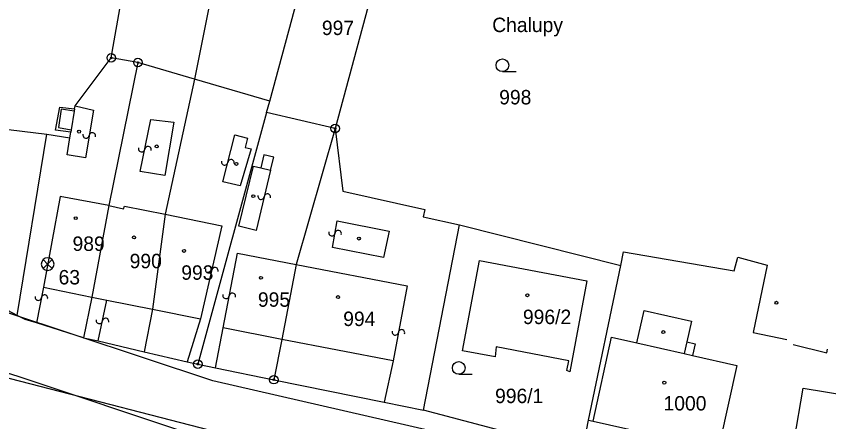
# Model space of a CAD drawing. Extents: x -469926 to -462499, y -1098642 to -1092733.
# Drawn here: x -465801.9 to -465706.1, y -1094414.1 to -1094366.3 of the extents above; entities that cross this region are included whole.
import ezdxf

# ---------------------------------------------------------------- set-up
doc = ezdxf.new("R2010")
doc.units = 0
for name, color, linetype in [('Vrstva 1', 7, 'Continuous'), ('Vrstva 14', 7, 'Continuous'), ('Vrstva 24', 7, 'Continuous'), ('Vrstva 25', 7, 'Continuous'), ('Vrstva 4', 7, 'Continuous'), ('Vrstva 50', 7, 'Continuous'), ('Vrstva 51', 7, 'Continuous'), ('Vrstva 8', 7, 'Continuous')]:
    doc.layers.add(name, color=color, linetype=linetype)

msp = doc.modelspace()

# ---------------------------------------------------------------- linework, layer by layer
at = {"layer": 'Vrstva 1'}
for p, q in [((-465790.66, -1094371.21), (-465786.86, -1094349.53)), ((-465776.39, -1094351.58), (-465780.87, -1094373.7)), ((-465771.99, -1094376.29), (-465765.81, -1094353.65)), ((-465757.73, -1094355.32), (-465764.28, -1094379.53)), ((-465794.93, -1094376.84), (-465790.66, -1094371.21)), ((-465794.93, -1094376.84), (-465790.66, -1094371.21)), ((-465787.52, -1094371.76), (-465790.94, -1094388.6)), ((-465787.52, -1094371.76), (-465790.94, -1094388.6)), ((-465787.52, -1094371.76), (-465790.66, -1094371.21)), ((-465787.52, -1094371.76), (-465790.66, -1094371.21)), ((-465780.87, -1094373.7), (-465787.52, -1094371.76)), ((-465780.87, -1094373.7), (-465787.52, -1094371.76)), ((-465780.87, -1094373.7), (-465784.33, -1094389.64)), ((-465780.87, -1094373.7), (-465784.33, -1094389.64)), ((-465771.99, -1094376.29), (-465780.87, -1094373.7)), ((-465771.99, -1094376.29), (-465780.87, -1094373.7)), ((-465794.98, -1094377.2), (-465794.93, -1094376.84)), ((-465794.98, -1094377.2), (-465794.93, -1094376.84)), ((-465772.36, -1094377.64), (-465771.99, -1094376.29)), ((-465772.36, -1094377.64), (-465771.99, -1094376.29)), ((-465797.22, -1094379.71), (-465796.74, -1094377.02)), ((-465797.22, -1094379.71), (-465796.74, -1094377.02)), ((-465796.74, -1094377.02), (-465794.98, -1094377.2)), ((-465796.74, -1094377.02), (-465794.98, -1094377.2)), ((-465772.36, -1094377.64), (-465780.46, -1094407.29)), ((-465772.36, -1094377.64), (-465780.46, -1094407.29)), ((-465764.28, -1094379.53), (-465772.36, -1094377.64)), ((-465764.28, -1094379.53), (-465772.36, -1094377.64)), ((-465812.27, -1094378.47), (-465798.24, -1094380.2)), ((-465812.27, -1094378.47), (-465798.24, -1094380.2)), ((-465795.43, -1094379.97), (-465797.22, -1094379.71)), ((-465795.43, -1094379.97), (-465797.22, -1094379.71)), ((-465764.28, -1094379.53), (-465768.87, -1094395.55)), ((-465764.28, -1094379.53), (-465768.87, -1094395.55)), ((-465764.28, -1094379.53), (-465763.36, -1094386.92)), ((-465764.28, -1094379.53), (-465763.36, -1094386.92)), ((-465801.74, -1094401.55), (-465798.24, -1094380.2)), ((-465801.74, -1094401.55), (-465798.24, -1094380.2)), ((-465798.24, -1094380.2), (-465795.54, -1094380.64)), ((-465798.24, -1094380.2), (-465795.54, -1094380.64)), ((-465795.54, -1094380.64), (-465795.43, -1094379.97)), ((-465795.54, -1094380.64), (-465795.43, -1094379.97)), ((-465763.36, -1094386.92), (-465753.69, -1094389.08)), ((-465763.36, -1094386.92), (-465753.69, -1094389.08)), ((-465790.94, -1094388.6), (-465792.95, -1094399.39)), ((-465790.94, -1094388.6), (-465792.95, -1094399.39)), ((-465753.69, -1094389.08), (-465753.92, -1094389.95)), ((-465753.69, -1094389.08), (-465753.92, -1094389.95)), ((-465784.33, -1094389.64), (-465785.79, -1094400.82)), ((-465784.33, -1094389.64), (-465785.79, -1094400.82)), ((-465753.92, -1094389.95), (-465749.62, -1094390.87)), ((-465753.92, -1094389.95), (-465749.62, -1094390.87)), ((-465753.87, -1094412.7), (-465749.62, -1094390.87)), ((-465753.87, -1094412.7), (-465749.62, -1094390.87)), ((-465749.62, -1094390.87), (-465730.62, -1094395.68)), ((-465749.62, -1094390.87), (-465730.62, -1094395.68)), ((-465730.62, -1094395.68), (-465730.29, -1094394.07)), ((-465730.62, -1094395.68), (-465730.29, -1094394.07)), ((-465730.29, -1094394.07), (-465717.26, -1094396.31)), ((-465730.29, -1094394.07), (-465717.26, -1094396.31)), ((-465801.74, -1094401.55), (-465814.21, -1094395.11)), ((-465801.74, -1094401.55), (-465814.21, -1094395.11)), ((-465749.27, -1094405.72), (-465747.25, -1094395.07)), ((-465749.27, -1094405.72), (-465747.25, -1094395.07)), ((-465747.25, -1094395.07), (-465734.63, -1094397.46)), ((-465747.25, -1094395.07), (-465734.63, -1094397.46)), ((-465717.26, -1094396.31), (-465716.83, -1094394.67)), ((-465717.26, -1094396.31), (-465716.83, -1094394.67)), ((-465716.83, -1094394.67), (-465713.36, -1094395.63)), ((-465716.83, -1094394.67), (-465713.36, -1094395.63)), ((-465768.87, -1094395.55), (-465770.57, -1094404.37)), ((-465768.87, -1094395.55), (-465770.57, -1094404.37)), ((-465734.4, -1094413.89), (-465730.62, -1094395.68)), ((-465734.4, -1094413.89), (-465730.62, -1094395.68)), ((-465734.63, -1094397.46), (-465736.6, -1094408.21)), ((-465734.63, -1094397.46), (-465736.6, -1094408.21)), ((-465792.95, -1094399.39), (-465793.93, -1094404.17)), ((-465792.95, -1094399.39), (-465793.93, -1094404.17)), ((-465785.79, -1094400.82), (-465786.79, -1094405.82)), ((-465785.79, -1094400.82), (-465786.79, -1094405.82)), ((-465800.82, -1094402.02), (-465801.74, -1094401.55)), ((-465800.82, -1094402.02), (-465801.74, -1094401.55)), ((-465799.49, -1094402.43), (-465800.82, -1094402.02)), ((-465799.49, -1094402.43), (-465800.82, -1094402.02)), ((-465793.93, -1094404.17), (-465799.49, -1094402.43)), ((-465793.93, -1094404.17), (-465799.49, -1094402.43)), ((-465793.93, -1094404.17), (-465792.21, -1094404.56)), ((-465793.93, -1094404.17), (-465792.21, -1094404.56)), ((-465792.21, -1094404.56), (-465786.79, -1094405.82)), ((-465792.21, -1094404.56), (-465786.79, -1094405.82)), ((-465770.57, -1094404.37), (-465771.5, -1094409.12)), ((-465770.57, -1094404.37), (-465771.5, -1094409.12)), ((-465745.3, -1094405.26), (-465745.41, -1094406.42)), ((-465745.3, -1094405.26), (-465745.41, -1094406.42)), ((-465736.75, -1094406.88), (-465745.3, -1094405.26)), ((-465736.75, -1094406.88), (-465745.3, -1094405.26)), ((-465786.79, -1094405.82), (-465781.7, -1094407.01)), ((-465786.79, -1094405.82), (-465781.7, -1094407.01)), ((-465745.41, -1094406.42), (-465749.27, -1094405.72)), ((-465745.41, -1094406.42), (-465749.27, -1094405.72)), ((-465781.7, -1094407.01), (-465780.46, -1094407.29)), ((-465781.7, -1094407.01), (-465780.46, -1094407.29)), ((-465780.46, -1094407.29), (-465778.38, -1094407.72)), ((-465780.46, -1094407.29), (-465778.38, -1094407.72)), ((-465736.97, -1094408.04), (-465736.75, -1094406.88)), ((-465736.97, -1094408.04), (-465736.75, -1094406.88)), ((-465778.38, -1094407.72), (-465771.5, -1094409.12)), ((-465778.38, -1094407.72), (-465771.5, -1094409.12)), ((-465736.6, -1094408.21), (-465736.97, -1094408.04)), ((-465736.6, -1094408.21), (-465736.97, -1094408.04)), ((-465766.38, -1094418.33), (-465803.8, -1094408.69)), ((-465766.38, -1094418.33), (-465803.8, -1094408.69)), ((-465771.5, -1094409.12), (-465758.48, -1094411.77)), ((-465771.5, -1094409.12), (-465758.48, -1094411.77)), ((-465758.48, -1094411.77), (-465753.87, -1094412.7)), ((-465758.48, -1094411.77), (-465753.87, -1094412.7)), ((-465735.18, -1094417.62), (-465753.87, -1094412.7)), ((-465735.18, -1094417.62), (-465753.87, -1094412.7)), ((-465735.18, -1094417.62), (-465734.4, -1094413.89)), ((-465735.18, -1094417.62), (-465734.4, -1094413.89)), ((-465734.4, -1094413.89), (-465733.86, -1094414.01)), ((-465734.4, -1094413.89), (-465733.86, -1094414.01)), ((-465733.86, -1094414.01), (-465719.12, -1094417.29)), ((-465733.86, -1094414.01), (-465719.12, -1094417.29))]:
    msp.add_line(p, q, dxfattribs=at)
at = {"layer": 'Vrstva 14'}
for p, q in [((-465848.124, -1094394.138), (-465801.662, -1094408.702)), ((-465848.124, -1094394.138), (-465801.662, -1094408.702)), ((-465801.662, -1094408.702), (-465781.335, -1094415.499)), ((-465801.662, -1094408.702), (-465781.335, -1094415.499))]:
    msp.add_line(p, q, dxfattribs=at)
at = {"layer": 'Vrstva 24'}
for p, q in [((-465798.69, -1094394.97), (-465798.16, -1094395.5)), ((-465798.69, -1094394.97), (-465798.16, -1094395.5)), ((-465797.63, -1094394.97), (-465798.16, -1094395.5)), ((-465797.63, -1094394.97), (-465798.16, -1094395.5)), ((-465798.16, -1094395.5), (-465798.69, -1094396.03)), ((-465798.16, -1094395.5), (-465798.69, -1094396.03)), ((-465798.16, -1094395.5), (-465797.63, -1094396.03)), ((-465798.16, -1094395.5), (-465797.63, -1094396.03))]:
    msp.add_line(p, q, dxfattribs=at)
for centre, radius in [((-465790.66, -1094371.21), 0.5), ((-465790.66, -1094371.21), 0.5), ((-465790.66, -1094371.21), 0.1), ((-465790.66, -1094371.21), 0.1), ((-465787.52, -1094371.76), 0.5), ((-465787.52, -1094371.76), 0.5), ((-465787.52, -1094371.76), 0.1), ((-465787.52, -1094371.76), 0.1), ((-465764.28, -1094379.53), 0.5), ((-465764.28, -1094379.53), 0.5), ((-465764.28, -1094379.53), 0.1), ((-465764.28, -1094379.53), 0.1), ((-465780.46, -1094407.29), 0.5), ((-465780.46, -1094407.29), 0.5), ((-465780.46, -1094407.29), 0.1), ((-465780.46, -1094407.29), 0.1), ((-465771.5, -1094409.12), 0.5), ((-465771.5, -1094409.12), 0.5), ((-465771.5, -1094409.12), 0.1), ((-465771.5, -1094409.12), 0.1)]:
    msp.add_circle(centre, radius, dxfattribs=at)
for radius, start, end in [(0.749, 135, 225), (0.749, 135, 225), (0.752, 45, 135), (0.752, 45, 135), (0.749, 315, 45), (0.749, 315, 45), (0.751, 225, 315), (0.751, 225, 315)]:
    msp.add_arc((-465798.16, -1094395.5), radius, start, end, dxfattribs=at)
at = {"layer": 'Vrstva 25'}
for p, q in [((-465744.56, -1094372.83), (-465742.96, -1094372.83)), ((-465749.71, -1094408.48), (-465748.11, -1094408.48)), ((-465749.71, -1094408.48), (-465748.11, -1094408.48))]:
    msp.add_line(p, q, dxfattribs=at)
for centre, radius in [((-465744.56, -1094372.08), 0.75), ((-465794.46, -1094379.9), 0.175), ((-465794.46, -1094379.9), 0.175), ((-465785.31, -1094381.64), 0.175), ((-465785.31, -1094381.64), 0.175), ((-465775.92, -1094383.7), 0.175), ((-465775.92, -1094383.7), 0.175), ((-465773.92, -1094387.5), 0.175), ((-465773.92, -1094387.5), 0.175), ((-465794.85, -1094390.09), 0.175), ((-465794.85, -1094390.09), 0.175), ((-465787.98, -1094392.36), 0.175), ((-465787.98, -1094392.36), 0.175), ((-465761.48, -1094392.5), 0.175), ((-465761.48, -1094392.5), 0.175), ((-465782.09, -1094393.95), 0.175), ((-465773.02, -1094397.12), 0.175), ((-465773.02, -1094397.12), 0.175), ((-465763.94, -1094399.39), 0.175), ((-465763.94, -1094399.39), 0.175), ((-465741.62, -1094399.17), 0.175), ((-465741.62, -1094399.17), 0.175), ((-465712.27, -1094400.06), 0.175), ((-465712.27, -1094400.06), 0.175), ((-465725.6, -1094403.51), 0.175), ((-465725.6, -1094403.51), 0.175), ((-465749.71, -1094407.73), 0.75), ((-465749.71, -1094407.73), 0.75), ((-465725.48, -1094409.47), 0.175), ((-465725.48, -1094409.47), 0.175)]:
    msp.add_circle(centre, radius, dxfattribs=at)
at = {"layer": 'Vrstva 4'}
for p, q in [((-465794.93, -1094376.84), (-465792.77, -1094377.35)), ((-465794.93, -1094376.84), (-465792.77, -1094377.35)), ((-465796.55, -1094377.26), (-465796.9, -1094379.42)), ((-465796.55, -1094377.26), (-465796.9, -1094379.42)), ((-465795.03, -1094377.5), (-465796.55, -1094377.26)), ((-465795.03, -1094377.5), (-465796.55, -1094377.26)), ((-465795.03, -1094377.5), (-465795.38, -1094379.67)), ((-465795.03, -1094377.5), (-465795.38, -1094379.67)), ((-465794.98, -1094377.2), (-465795.03, -1094377.5)), ((-465794.98, -1094377.2), (-465795.03, -1094377.5)), ((-465792.77, -1094377.35), (-465793.69, -1094382.98)), ((-465792.77, -1094377.35), (-465793.69, -1094382.98)), ((-465787.24, -1094384.58), (-465785.99, -1094378.45)), ((-465787.24, -1094384.58), (-465785.99, -1094378.45)), ((-465785.99, -1094378.45), (-465783.29, -1094378.78)), ((-465785.99, -1094378.45), (-465783.29, -1094378.78)), ((-465783.29, -1094378.78), (-465784.36, -1094385.07)), ((-465783.29, -1094378.78), (-465784.36, -1094385.07)), ((-465796.9, -1094379.42), (-465795.38, -1094379.67)), ((-465796.9, -1094379.42), (-465795.38, -1094379.67)), ((-465795.38, -1094379.67), (-465795.43, -1094379.97)), ((-465795.38, -1094379.67), (-465795.43, -1094379.97)), ((-465795.86, -1094382.64), (-465795.54, -1094380.64)), ((-465795.86, -1094382.64), (-465795.54, -1094380.64)), ((-465777.51, -1094385.81), (-465776.09, -1094380.29)), ((-465777.51, -1094385.81), (-465776.09, -1094380.29)), ((-465776.09, -1094380.29), (-465774.61, -1094380.65)), ((-465776.09, -1094380.29), (-465774.61, -1094380.65)), ((-465774.61, -1094380.65), (-465774.89, -1094381.75)), ((-465774.61, -1094380.65), (-465774.89, -1094381.75)), ((-465793.69, -1094382.98), (-465795.86, -1094382.64)), ((-465793.69, -1094382.98), (-465795.86, -1094382.64)), ((-465774.19, -1094381.93), (-465775.46, -1094386.3)), ((-465774.19, -1094381.93), (-465775.46, -1094386.3)), ((-465774.89, -1094381.75), (-465774.19, -1094381.93)), ((-465774.89, -1094381.75), (-465774.19, -1094381.93)), ((-465772.67, -1094382.64), (-465773.04, -1094384.17)), ((-465772.67, -1094382.64), (-465773.04, -1094384.17)), ((-465771.51, -1094382.92), (-465772.67, -1094382.64)), ((-465771.51, -1094382.92), (-465772.67, -1094382.64)), ((-465771.88, -1094384.45), (-465771.51, -1094382.92)), ((-465771.88, -1094384.45), (-465771.51, -1094382.92)), ((-465784.36, -1094385.07), (-465787.24, -1094384.58)), ((-465784.36, -1094385.07), (-465787.24, -1094384.58)), ((-465775.63, -1094391.04), (-465773.91, -1094383.96)), ((-465775.63, -1094391.04), (-465773.91, -1094383.96)), ((-465773.91, -1094383.96), (-465773.04, -1094384.17)), ((-465773.91, -1094383.96), (-465773.04, -1094384.17)), ((-465771.88, -1094384.45), (-465773.6, -1094391.53)), ((-465771.88, -1094384.45), (-465773.6, -1094391.53)), ((-465773.04, -1094384.17), (-465771.88, -1094384.45)), ((-465773.04, -1094384.17), (-465771.88, -1094384.45)), ((-465775.46, -1094386.3), (-465777.51, -1094385.81)), ((-465775.46, -1094386.3), (-465777.51, -1094385.81)), ((-465796.69, -1094387.53), (-465798.66, -1094398.23)), ((-465796.69, -1094387.53), (-465798.66, -1094398.23)), ((-465790.94, -1094388.6), (-465796.69, -1094387.53)), ((-465790.94, -1094388.6), (-465796.69, -1094387.53)), ((-465790.94, -1094388.6), (-465789.21, -1094389.01)), ((-465790.94, -1094388.6), (-465789.21, -1094389.01)), ((-465789.21, -1094389.01), (-465789.12, -1094388.66)), ((-465789.21, -1094389.01), (-465789.12, -1094388.66)), ((-465789.12, -1094388.66), (-465784.33, -1094389.64)), ((-465789.12, -1094388.66), (-465784.33, -1094389.64)), ((-465784.33, -1094389.64), (-465777.62, -1094390.99)), ((-465784.33, -1094389.64), (-465777.62, -1094390.99)), ((-465777.62, -1094390.99), (-465780.13, -1094401.95)), ((-465777.62, -1094390.99), (-465780.13, -1094401.95)), ((-465773.6, -1094391.53), (-465775.63, -1094391.04)), ((-465773.6, -1094391.53), (-465775.63, -1094391.04)), ((-465764.59, -1094393.56), (-465764.03, -1094390.42)), ((-465764.59, -1094393.56), (-465764.03, -1094390.42)), ((-465764.03, -1094390.42), (-465757.91, -1094391.61)), ((-465764.03, -1094390.42), (-465757.91, -1094391.61)), ((-465757.91, -1094391.61), (-465758.58, -1094394.71)), ((-465757.91, -1094391.61), (-465758.58, -1094394.71)), ((-465758.58, -1094394.71), (-465764.59, -1094393.56)), ((-465758.58, -1094394.71), (-465764.59, -1094393.56)), ((-465777.49, -1094403.03), (-465775.8, -1094394.22)), ((-465777.49, -1094403.03), (-465775.8, -1094394.22)), ((-465775.8, -1094394.22), (-465768.87, -1094395.55)), ((-465775.8, -1094394.22), (-465768.87, -1094395.55)), ((-465768.87, -1094395.55), (-465755.8, -1094398.06)), ((-465768.87, -1094395.55), (-465755.8, -1094398.06)), ((-465713.36, -1094395.63), (-465715.02, -1094403.55)), ((-465713.36, -1094395.63), (-465715.02, -1094403.55)), ((-465798.66, -1094398.23), (-465799.49, -1094402.43)), ((-465798.66, -1094398.23), (-465799.49, -1094402.43)), ((-465798.66, -1094398.23), (-465792.95, -1094399.39)), ((-465798.66, -1094398.23), (-465792.95, -1094399.39)), ((-465755.8, -1094398.06), (-465757.45, -1094406.91)), ((-465755.8, -1094398.06), (-465757.45, -1094406.91)), ((-465792.95, -1094399.39), (-465791.18, -1094399.74)), ((-465792.95, -1094399.39), (-465791.18, -1094399.74)), ((-465792.21, -1094404.56), (-465791.18, -1094399.74)), ((-465792.21, -1094404.56), (-465791.18, -1094399.74)), ((-465791.18, -1094399.74), (-465785.79, -1094400.82)), ((-465791.18, -1094399.74), (-465785.79, -1094400.82)), ((-465785.79, -1094400.82), (-465780.13, -1094401.95)), ((-465785.79, -1094400.82), (-465780.13, -1094401.95)), ((-465728.73, -1094404.79), (-465727.86, -1094400.96)), ((-465728.73, -1094404.79), (-465727.86, -1094400.96)), ((-465727.86, -1094400.96), (-465722.29, -1094402.24)), ((-465727.86, -1094400.96), (-465722.29, -1094402.24)), ((-465780.13, -1094401.95), (-465781.7, -1094407.01)), ((-465780.13, -1094401.95), (-465781.7, -1094407.01)), ((-465722.29, -1094402.24), (-465722.84, -1094404.68)), ((-465722.29, -1094402.24), (-465722.84, -1094404.68)), ((-465778.38, -1094407.72), (-465777.49, -1094403.03)), ((-465778.38, -1094407.72), (-465777.49, -1094403.03)), ((-465770.57, -1094404.37), (-465777.49, -1094403.03)), ((-465770.57, -1094404.37), (-465777.49, -1094403.03)), ((-465715.02, -1094403.55), (-465711.04, -1094404.37)), ((-465715.02, -1094403.55), (-465711.04, -1094404.37)), ((-465757.45, -1094406.91), (-465770.57, -1094404.37)), ((-465757.45, -1094406.91), (-465770.57, -1094404.37)), ((-465733.86, -1094414.01), (-465731.7, -1094404.12)), ((-465733.86, -1094414.01), (-465731.7, -1094404.12)), ((-465731.7, -1094404.12), (-465728.73, -1094404.79)), ((-465731.7, -1094404.12), (-465728.73, -1094404.79)), ((-465722.84, -1094404.68), (-465723.15, -1094406.04)), ((-465722.84, -1094404.68), (-465723.15, -1094406.04)), ((-465722.84, -1094404.68), (-465721.86, -1094404.9)), ((-465722.84, -1094404.68), (-465721.86, -1094404.9)), ((-465728.73, -1094404.79), (-465723.15, -1094406.04)), ((-465728.73, -1094404.79), (-465723.15, -1094406.04)), ((-465721.86, -1094404.9), (-465722.17, -1094406.26)), ((-465721.86, -1094404.9), (-465722.17, -1094406.26)), ((-465710.28, -1094404.99), (-465706.33, -1094405.94)), ((-465710.28, -1094404.99), (-465706.33, -1094405.94)), ((-465706.33, -1094405.94), (-465706.23, -1094405.52)), ((-465706.33, -1094405.94), (-465706.23, -1094405.52)), ((-465723.15, -1094406.04), (-465722.17, -1094406.26)), ((-465723.15, -1094406.04), (-465722.17, -1094406.26)), ((-465722.17, -1094406.26), (-465716.94, -1094407.44)), ((-465722.17, -1094406.26), (-465716.94, -1094407.44)), ((-465757.45, -1094406.91), (-465758.48, -1094411.77)), ((-465757.45, -1094406.91), (-465758.48, -1094411.77)), ((-465716.94, -1094407.44), (-465719.12, -1094417.29)), ((-465716.94, -1094407.44), (-465719.12, -1094417.29)), ((-465710.67, -1094419.14), (-465709.1, -1094410.13)), ((-465710.67, -1094419.14), (-465709.1, -1094410.13)), ((-465709.1, -1094410.13), (-465703.25, -1094411.07)), ((-465709.1, -1094410.13), (-465703.25, -1094411.07))]:
    msp.add_line(p, q, dxfattribs=at)
at = {"layer": 'Vrstva 51'}
for centre, radius, start, end in [((-465793.633, -1094380.3), 0.376, 165.44036, 351.75149), ((-465793.633, -1094380.3), 0.376, 165.44036, 351.75149), ((-465792.887, -1094380.403), 0.377, 344.76432, 172.42753), ((-465792.887, -1094380.403), 0.377, 344.76432, 172.42753), ((-465786.333, -1094382.014), 0.377, 344.76432, 172.42753), ((-465786.333, -1094382.014), 0.377, 344.76432, 172.42753), ((-465787.079, -1094381.91), 0.376, 165.44036, 351.75149), ((-465787.079, -1094381.91), 0.376, 165.44036, 351.75149), ((-465777.293, -1094383.465), 0.376, 165.44036, 351.75149), ((-465777.293, -1094383.465), 0.376, 165.44036, 351.75149), ((-465776.547, -1094383.569), 0.377, 344.76432, 172.42753), ((-465776.547, -1094383.569), 0.377, 344.76432, 172.42753), ((-465773.008, -1094387.506), 0.376, 165.44036, 351.75149), ((-465773.008, -1094387.506), 0.376, 165.44036, 351.75149), ((-465772.262, -1094387.609), 0.377, 344.76432, 172.42753), ((-465772.262, -1094387.609), 0.377, 344.76432, 172.42753), ((-465764.658, -1094391.8), 0.376, 165.44036, 351.75149), ((-465764.658, -1094391.8), 0.376, 165.44036, 351.75149), ((-465763.912, -1094391.904), 0.377, 344.76432, 172.42753), ((-465763.912, -1094391.904), 0.377, 344.76432, 172.42753), ((-465779.192, -1094396.173), 0.376, 165.44036, 351.75149), ((-465779.192, -1094396.173), 0.376, 165.44036, 351.75149), ((-465778.446, -1094396.276), 0.377, 344.76432, 172.42753), ((-465778.446, -1094396.276), 0.377, 344.76432, 172.42753), ((-465776.391, -1094399.299), 0.377, 344.76432, 172.42753), ((-465776.391, -1094399.299), 0.377, 344.76432, 172.42753), ((-465799.274, -1094399.399), 0.376, 165.44036, 351.75149), ((-465799.274, -1094399.399), 0.376, 165.44036, 351.75149), ((-465798.528, -1094399.503), 0.377, 344.76432, 172.42753), ((-465798.528, -1094399.503), 0.377, 344.76432, 172.42753), ((-465777.137, -1094399.195), 0.376, 165.44036, 351.75149), ((-465777.137, -1094399.195), 0.376, 165.44036, 351.75149), ((-465792.078, -1094402.144), 0.376, 165.44036, 351.75149), ((-465792.078, -1094402.144), 0.376, 165.44036, 351.75149), ((-465791.332, -1094402.247), 0.377, 344.76432, 172.42753), ((-465791.332, -1094402.247), 0.377, 344.76432, 172.42753), ((-465757.196, -1094403.497), 0.376, 165.44036, 351.75149), ((-465757.196, -1094403.497), 0.376, 165.44036, 351.75149), ((-465756.45, -1094403.601), 0.377, 344.76432, 172.42753), ((-465756.45, -1094403.601), 0.377, 344.76432, 172.42753)]:
    msp.add_arc(centre, radius, start, end, dxfattribs=at)
at = {"layer": 'Vrstva 8'}
for p, q in [((-465778.69, -1094409.252), (-465803.103, -1094401.157)), ((-465778.69, -1094409.252), (-465803.103, -1094401.157)), ((-465546.608, -1094462.403), (-465778.69, -1094409.252))]:
    msp.add_line(p, q, dxfattribs=at)

# ---------------------------------------------------------------- texts
at = {"layer": 'Vrstva 50'}
for s, p in [('Chalupy', (-465745.766, -1094368.17)), ('997', (-465765.84, -1094368.52)), ('998', (-465744.943, -1094376.69)), ('989', (-465795.227, -1094393.95)), ('990', (-465788.493, -1094395.99)), ('993', (-465782.414, -1094397.35)), ('63', (-465796.87, -1094397.9)), ('63', (-465796.87, -1094397.9)), ('995', (-465773.38, -1094400.53)), ('996/2', (-465742.145, -1094402.57)), ('994', (-465763.326, -1094402.8)), ('996/1', (-465745.429, -1094411.88)), ('1000', (-465725.573, -1094412.75))]:
    msp.add_text(s, height=1.7, dxfattribs=at).set_placement(p)

doc.saveas('drawing.dxf')
